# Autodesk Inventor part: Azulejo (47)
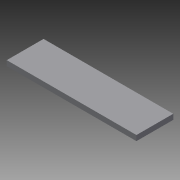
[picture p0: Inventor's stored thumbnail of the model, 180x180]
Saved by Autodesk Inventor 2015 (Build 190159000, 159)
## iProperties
Created: 2015-04
Part Number: Azulejo (47)
Material: Genérico
Document SubType Name: Modeling
Designer: Felipe
Density: 1 g/cm^3
Appearance: Padrão
Author: Felipe
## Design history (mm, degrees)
sketch "Sketch1"
  geometry: L1 (-5999.978, 1162.687)-(-5915.126, 1162.687); L2 (6980.022, 1162.687)-(6895.169, 1162.687); L3 (-1034.12, -6357.313)-(-1063.775, -6417.313); L4 (-5519.978, 1582.687)-(-6306.841, 1582.687); L5 (5000.022, -4857.313)-(6000.022, -4857.313); L6 (6000.022, -4857.313)-(6000.022, -6277.313); L7 (6000.022, -4837.313)-(5000.022, -4837.313); L8 (5000.022, -4837.313)-(5000.022, -3357.313); L9 (5000.022, -3357.313)-(6000.022, -3357.313); L10 (6000.022, -3357.313)-(6000.022, -4837.313); L11 (6000.022, -3337.313)-(5000.022, -3337.313); L12 (5000.022, -3337.313)-(5000.022, -1857.313); L13 (5000.022, -1857.313)-(6000.022, -1857.313); L14 (6000.022, -1857.313)-(6000.022, -3337.313); L15 (6000.022, -1837.313)-(5000.022, -1837.313); L16 (5000.022, -1837.313)-(5000.022, -357.313); L17 (5000.022, -357.313)-(6000.022, -357.313); L18 (6000.022, -357.313)-(6000.022, -1837.313); L19 (4000.022, -4837.313)-(3500.022, -4837.313); L20 (3500.022, -4837.313)-(3500.022, -3357.313); L21 (3500.022, -3357.313)-(4000.022, -3357.313); L22 (4000.022, -3357.313)-(4000.022, -4837.313); L23 (4000.022, -3337.313)-(3500.022, -3337.313); L24 (3500.022, -3337.313)-(3500.022, -1857.313); L25 (2000.022, 2662.687)-(2480.022, 2662.687); L26 (500.022, 2662.687)-(1980.022, 2662.687); L27 (-999.978, 2662.687)-(480.022, 2662.687); L28 (3500.022, -1857.313)-(4000.022, -1857.313); L29 (4000.022, -1857.313)-(4000.022, -3337.313); L30 (4000.022, -1837.313)-(3500.022, -1837.313); L31 (3500.022, -1837.313)-(3500.022, -357.313); L32 (3500.022, -357.313)-(4000.022, -357.313); L33 (4000.022, -357.313)-(4000.022, -1837.313); L34 (-5519.978, 1142.687)-(-5519.978, -337.313); L35 (6500.022, -337.313)-(6500.022, 1142.687); L36 (6480.022, 2662.687)-(5000.022, 2662.687); L37 (5000.022, 2642.687)-(6480.022, 2642.687); L38 (6480.022, 1142.687)-(6480.022, -337.313); L39 (6480.022, -337.313)-(5000.022, -337.313); L40 (5000.022, -337.313)-(5000.022, 1142.687); L41 (7965.922, 2662.687)-(6500.022, 2662.687); L42 (6500.022, 2642.687)-(7965.922, 2642.687); L43 (4980.022, 2662.687)-(3500.022, 2662.687); L44 (3500.022, 2642.687)-(4980.022, 2642.687); L45 (4980.022, 1142.687)-(4980.022, -337.313); L46 (4980.022, -337.313)-(3500.022, -337.313); L47 (3500.022, -337.313)-(3500.022, 1142.687); L48 (3500.022, -1837.313)-(3500.022, -357.313); L49 (3500.022, -3337.313)-(3500.022, -1857.313); L50 (3500.022, -4837.313)-(3500.022, -3357.313); L51 (3500.022, -6257.313)-(3500.022, -4857.313); L52 (4000.022, -6277.313)-(3500.022, -6277.313); L53 (3500.022, -6277.313)-(3500.022, -4857.313); L54 (3480.022, 1162.687)-(2000.022, 1162.687); L55 (2000.022, 1142.687)-(3480.022, 1142.687); L56 (3480.022, 1142.687)-(3480.022, -337.313); L57 (3480.022, -337.313)-(2000.022, -337.313); L58 (2000.022, -337.313)-(2000.022, 1142.687); L59 (3480.022, -357.313)-(3480.022, -1837.313); L60 (3480.022, -1857.313)-(3480.022, -3337.313); L61 (3480.022, -3357.313)-(3480.022, -4837.313); L62 (3480.022, -4857.313)-(3480.022, -6277.313); L63 (3500.022, -4857.313)-(4000.022, -4857.313); L64 (1980.022, 1162.687)-(500.022, 1162.687)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; 4 further points
  constraints: 1802 end point, 96 point on line, 2 other
extrude "Extrusion1" new body sketch "Sketch1" distance "d0" = 60; taper "d1" = 0 deg
body "Solid1"
